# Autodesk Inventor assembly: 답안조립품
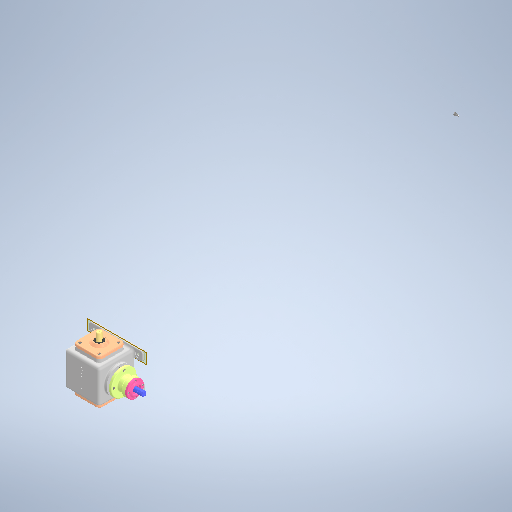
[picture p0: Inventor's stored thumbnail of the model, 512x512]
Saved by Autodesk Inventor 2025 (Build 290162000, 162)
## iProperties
Created: 2026-01
Part Number: 답안조립품
Document SubType Name: Assembly
Designer: KDI
Author: KDI
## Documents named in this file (17)
- C:\Users\KDI\Desktop\760103V1017\답안조립품.iam
- C:\Users\KDI\Desktop\760103V1017\본체.ipt
- C:\Users\KDI\Desktop\760103V1017\6각 구멍붙이 볼트 M4x10\6각 구멍붙이 볼트 M4x10.ipt
- C:\Users\KDI\Desktop\760103V1017\6각 구멍붙이 볼트 M6x12\6각 구멍붙이 볼트 M6x12.ipt
- C:\Users\KDI\Desktop\760103V1017\구동축\구동축.ipt
- C:\Users\KDI\Desktop\760103V1017\베벨 기어(구동)\베벨 기어(구동).ipt
- C:\Users\KDI\Desktop\760103V1017\베벨 기어(종동)\베벨 기어(종동).ipt
- C:\Users\KDI\Desktop\760103V1017\베어링 하우징\베어링 하우징.ipt
- C:\Users\KDI\Desktop\760103V1017\엔드캡\엔드캡.ipt
- C:\Users\KDI\Desktop\760103V1017\오일 실 20 35 8\오일 실 20 35 8.ipt
- C:\Users\KDI\Desktop\760103V1017\종동축\종동축.ipt
- C:\Users\KDI\Desktop\760103V1017\측면 커버\측면 커버.ipt
- C:\Users\KDI\Desktop\760103V1017\칼라\칼라.ipt
- C:\Users\KDI\Desktop\760103V1017\테이퍼 롤러 베어링 30204K\테이퍼 롤러 베어링 30204K.ipt
- C:\Users\KDI\Desktop\760103V1017\평행 키 6x6x18\평행 키 6x6x18.ipt
- C:\Users\KDI\Desktop\760103V1017\하우징 커버\하우징 커버.ipt
- C:\Users\KDI\Desktop\760103V1017\6각 구멍붙이 볼트 M6x12\6각 구멍붙이 볼트 M6x12_MIR.ipt
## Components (20 placed, 5 different names)
1. 구동축:1 — 각도:5
2. 하우징 커버:1
3. 6각 구멍붙이 볼트 M6x12_MIR:1
4. 6각 구멍붙이 볼트 M6x12_MIR:2
5. 6각 구멍붙이 볼트 M6x12_MIR:3
6. 6각 구멍붙이 볼트 M6x12_MIR:4
7. 6각 구멍붙이 볼트 M6x12:11
8. 6각 구멍붙이 볼트 M6x12:12
9. 6각 구멍붙이 볼트 M6x12:2
10. 6각 구멍붙이 볼트 M6x12:3
11. 6각 구멍붙이 볼트 M6x12:4
12. 6각 구멍붙이 볼트 M6x12:5
13. 6각 구멍붙이 볼트 M6x12:7
14. 6각 구멍붙이 볼트 M6x12:8
15. 6각 구멍붙이 볼트 M6x12:9
16. 6각 구멍붙이 볼트 M6x12:10
17. 6각 구멍붙이 볼트 M4x10:1
18. 6각 구멍붙이 볼트 M4x10:2
19. 6각 구멍붙이 볼트 M4x10:3
20. 6각 구멍붙이 볼트 M4x10:4
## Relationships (1: Angle 1)
- 각도:5 [Angle]: 구동축:1
